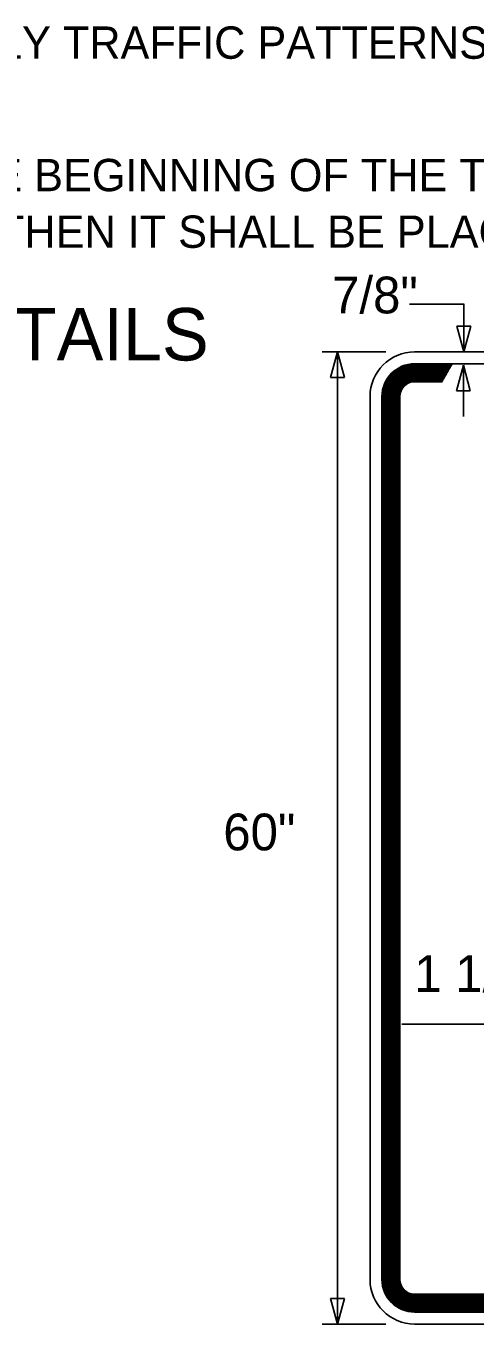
# Model space of a CAD drawing. Extents: x 15262 to 18126, y 1908 to 6555.
# Drawn here: x 17745 to 17847.7, y 2366.5 to 2663.3 of the extents above; entities that cross this region are included whole.
import ezdxf

# ---------------------------------------------------------------- set-up
doc = ezdxf.new("R2010")
doc.units = 0
doc.layers.add('TYPICAL_EX', color=7, linetype='Continuous')
doc.layers.add('TYPICAL_TEXT_DIMEN_PR', color=7, linetype='Continuous')

msp = doc.modelspace()

# ---------------------------------------------------------------- linework, layer by layer
at = {"layer": 'TYPICAL_EX'}
for p, q in [((17976.4, 2588.82), (17833.88, 2588.82)), ((17842.58, 2586.1), (17833.89, 2586.1)), ((17842.52, 2585.99), (17833.89, 2585.99)), ((17842.45, 2585.88), (17833.89, 2585.88)), ((17842.39, 2585.77), (17833.89, 2585.77)), ((17842.32, 2585.66), (17833.89, 2585.66)), ((17842.26, 2585.54), (17833.89, 2585.54)), ((17842.19, 2585.43), (17833.89, 2585.43)), ((17842.13, 2585.32), (17833.89, 2585.32)), ((17846.51, 2586.1), (17842.51, 2586.1)), ((17976.4, 2586.1), (17846.51, 2586.1)), ((17842.06, 2585.21), (17833.89, 2585.21)), ((17842, 2585.1), (17833.89, 2585.1)), ((17841.94, 2584.98), (17833.89, 2584.98)), ((17841.87, 2584.87), (17833.89, 2584.87)), ((17841.81, 2584.76), (17833.89, 2584.76)), ((17841.74, 2584.65), (17833.89, 2584.65)), ((17841.68, 2584.53), (17833.89, 2584.53)), ((17841.61, 2584.42), (17833.89, 2584.42)), ((17841.55, 2584.31), (17833.89, 2584.31)), ((17841.48, 2584.2), (17833.89, 2584.2)), ((17841.42, 2584.09), (17833.89, 2584.09)), ((17841.35, 2583.97), (17833.89, 2583.97)), ((17841.29, 2583.86), (17833.89, 2583.86)), ((17841.22, 2583.75), (17833.89, 2583.75)), ((17841.16, 2583.64), (17833.89, 2583.64)), ((17841.1, 2583.53), (17833.89, 2583.53)), ((17841.03, 2583.41), (17833.89, 2583.41)), ((17840.97, 2583.3), (17833.89, 2583.3)), ((17840.9, 2583.19), (17833.89, 2583.19)), ((17840.84, 2583.08), (17833.89, 2583.08)), ((17840.77, 2582.97), (17833.89, 2582.97)), ((17840.71, 2582.85), (17833.89, 2582.85)), ((17840.64, 2582.74), (17833.89, 2582.74)), ((17840.58, 2582.63), (17833.89, 2582.63)), ((17840.51, 2582.52), (17833.89, 2582.52)), ((17840.45, 2582.41), (17833.89, 2582.41)), ((17840.39, 2582.29), (17833.89, 2582.29)), ((17840.32, 2582.18), (17833.89, 2582.18)), ((17840.26, 2582.07), (17833.89, 2582.07)), ((17840.21, 2581.99), (17833.89, 2581.99)), ((17823.7, 2578.64), (17823.7, 2430.55)), ((17826.42, 2578.64), (17826.42, 2430.55)), ((17826.53, 2578.64), (17826.53, 2430.55)), ((17826.64, 2578.64), (17826.64, 2430.55)), ((17826.76, 2578.64), (17826.76, 2430.55)), ((17826.87, 2578.64), (17826.87, 2430.42)), ((17826.98, 2578.64), (17826.98, 2430.55)), ((17827.09, 2578.64), (17827.09, 2430.55)), ((17827.2, 2578.64), (17827.2, 2430.53)), ((17827.32, 2578.64), (17827.32, 2430.56)), ((17827.43, 2578.64), (17827.43, 2430.51)), ((17827.54, 2578.64), (17827.54, 2430.55)), ((17827.65, 2578.64), (17827.65, 2430.55)), ((17827.76, 2578.64), (17827.76, 2430.59)), ((17827.88, 2578.64), (17827.88, 2430.55)), ((17827.99, 2578.64), (17827.99, 2430.55)), ((17828.1, 2578.64), (17828.1, 2430.55)), ((17828.21, 2578.64), (17828.21, 2430.55)), ((17828.33, 2578.64), (17828.33, 2430.55)), ((17828.44, 2578.64), (17828.44, 2430.54)), ((17828.55, 2578.64), (17828.55, 2430.55)), ((17828.66, 2578.64), (17828.66, 2430.56)), ((17828.77, 2578.64), (17828.77, 2430.55)), ((17828.89, 2578.64), (17828.89, 2430.55)), ((17829, 2578.64), (17829, 2430.54)), ((17829.11, 2578.64), (17829.11, 2430.57)), ((17829.22, 2578.64), (17829.22, 2430.55)), ((17829.33, 2578.64), (17829.33, 2430.55)), ((17829.44, 2578.64), (17829.44, 2449.25)), ((17829.56, 2578.64), (17829.56, 2449.25)), ((17829.67, 2578.64), (17829.67, 2449.25)), ((17829.78, 2578.64), (17829.78, 2430.55)), ((17829.89, 2578.64), (17829.89, 2430.54)), ((17830.01, 2578.64), (17830.01, 2430.55)), ((17830.12, 2578.64), (17830.12, 2430.54)), ((17830.23, 2578.64), (17830.23, 2430.55)), ((17830.34, 2578.64), (17830.34, 2430.57)), ((17830.45, 2578.64), (17830.45, 2430.56)), ((17830.53, 2578.64), (17830.53, 2430.57)), ((17829.44, 2449.33), (17829.44, 2376.7)), ((17829.56, 2449.25), (17829.56, 2376.7)), ((17829.67, 2449.25), (17829.67, 2376.7)), ((17830.94, 2435.12), (17979.69, 2435.12)), ((17823.7, 2430.55), (17823.7, 2376.7)), ((17826.42, 2430.55), (17826.42, 2376.7)), ((17826.53, 2430.55), (17826.53, 2376.7)), ((17826.64, 2430.55), (17826.64, 2376.7)), ((17826.76, 2430.55), (17826.76, 2376.7)), ((17826.87, 2430.55), (17826.87, 2376.7)), ((17826.98, 2430.55), (17826.98, 2376.7)), ((17827.09, 2430.55), (17827.09, 2376.7)), ((17827.2, 2430.55), (17827.2, 2376.03)), ((17827.32, 2430.55), (17827.32, 2376.7)), ((17827.43, 2430.55), (17827.43, 2376.7)), ((17827.54, 2430.55), (17827.54, 2376.7)), ((17827.65, 2430.55), (17827.65, 2376.7)), ((17827.76, 2430.6), (17827.76, 2376.7)), ((17827.88, 2430.55), (17827.88, 2376.7)), ((17827.99, 2430.55), (17827.99, 2376.7)), ((17828.1, 2430.55), (17828.1, 2376.7)), ((17828.21, 2430.55), (17828.21, 2376.7)), ((17828.33, 2430.55), (17828.33, 2376.7)), ((17828.44, 2430.55), (17828.44, 2376.7)), ((17828.55, 2430.55), (17828.55, 2376.7)), ((17828.66, 2430.55), (17828.66, 2376.7)), ((17828.77, 2430.55), (17828.77, 2376.7)), ((17828.89, 2430.55), (17828.89, 2376.7)), ((17829, 2430.55), (17829, 2376.7)), ((17829.11, 2430.55), (17829.11, 2376.7)), ((17829.22, 2430.55), (17829.22, 2376.7)), ((17829.33, 2430.55), (17829.33, 2376.7)), ((17829.78, 2430.55), (17829.78, 2376.7)), ((17829.89, 2430.55), (17829.89, 2376.7)), ((17830.01, 2430.55), (17830.01, 2376.7)), ((17830.12, 2430.54), (17830.12, 2376.7)), ((17830.23, 2430.55), (17830.23, 2376.7)), ((17830.34, 2430.55), (17830.34, 2376.7)), ((17830.45, 2430.55), (17830.45, 2376.7)), ((17830.53, 2430.55), (17830.53, 2376.7)), ((17833.88, 2373.35), (17976.4, 2373.35)), ((17833.88, 2373.27), (17976.4, 2373.27)), ((17833.88, 2373.16), (17976.4, 2373.16)), ((17833.88, 2373.05), (17976.4, 2373.05)), ((17833.88, 2372.94), (17976.4, 2372.94)), ((17833.88, 2372.83), (17976.4, 2372.83)), ((17833.88, 2372.71), (17976.4, 2372.71)), ((17833.88, 2372.6), (17976.4, 2372.6)), ((17833.88, 2372.49), (17976.4, 2372.49)), ((17833.88, 2372.38), (17976.4, 2372.38)), ((17833.88, 2372.27), (17976.4, 2372.27)), ((17833.88, 2372.15), (17976.4, 2372.15)), ((17833.88, 2372.04), (17976.4, 2372.04)), ((17833.88, 2371.93), (17976.4, 2371.93)), ((17833.88, 2371.82), (17976.4, 2371.82)), ((17833.88, 2371.7), (17976.4, 2371.7)), ((17833.88, 2371.59), (17976.4, 2371.59)), ((17833.88, 2371.48), (17976.4, 2371.48)), ((17833.88, 2371.37), (17976.4, 2371.37)), ((17833.88, 2371.26), (17976.4, 2371.26)), ((17833.88, 2371.14), (17976.4, 2371.14)), ((17833.88, 2371.03), (17976.4, 2371.03)), ((17833.88, 2370.92), (17976.4, 2370.92)), ((17833.88, 2370.81), (17976.4, 2370.81)), ((17833.88, 2370.7), (17976.4, 2370.7)), ((17833.88, 2370.59), (17976.4, 2370.59)), ((17833.88, 2370.47), (17976.4, 2370.47)), ((17833.88, 2370.36), (17976.4, 2370.36)), ((17833.88, 2370.25), (17976.4, 2370.25)), ((17833.88, 2370.14), (17976.4, 2370.14)), ((17833.88, 2370.02), (17976.4, 2370.02)), ((17833.88, 2369.91), (17976.4, 2369.91)), ((17833.88, 2369.8), (17976.4, 2369.8)), ((17833.88, 2369.69), (17976.4, 2369.69)), ((17833.88, 2369.58), (17976.4, 2369.58)), ((17833.88, 2369.46), (17976.4, 2369.46)), ((17833.88, 2369.35), (17976.4, 2369.35)), ((17833.88, 2369.24), (17976.4, 2369.24)), ((17833.88, 2366.53), (17976.4, 2366.53))]:
    msp.add_line(p, q, dxfattribs=at)
for centre, radius, start, end in [((17833.88, 2578.64), 10.18, 90, 180), ((17833.88, 2578.64), 7.46, 90, 180), ((17833.88, 2578.64), 7.35, 90, 180), ((17833.88, 2578.64), 7.24, 90, 180), ((17833.88, 2578.64), 7.13, 90, 180), ((17833.88, 2578.64), 7.02, 90, 180), ((17833.88, 2578.64), 6.9, 90, 180), ((17833.88, 2578.64), 6.79, 90, 180), ((17833.88, 2578.64), 6.68, 90, 180), ((17833.88, 2578.64), 6.57, 90, 180), ((17833.88, 2578.64), 6.46, 90, 180), ((17833.88, 2578.64), 6.34, 90, 180), ((17833.88, 2578.64), 6.23, 90, 180), ((17833.88, 2578.64), 6.12, 90, 180), ((17833.88, 2578.64), 6.01, 90, 180), ((17833.88, 2578.64), 5.9, 90, 180), ((17833.88, 2578.64), 5.78, 90, 180), ((17833.88, 2578.64), 5.67, 90, 180), ((17833.88, 2578.64), 5.56, 90, 180), ((17833.88, 2578.64), 5.45, 90, 180), ((17833.88, 2578.64), 5.34, 90, 180), ((17833.88, 2578.64), 5.22, 90, 180), ((17833.88, 2578.64), 5.11, 90, 180), ((17833.88, 2578.64), 5, 90, 180), ((17833.88, 2578.64), 4.89, 90, 180), ((17833.88, 2578.64), 4.78, 90, 180), ((17833.88, 2578.64), 4.66, 90, 180), ((17833.88, 2578.64), 4.55, 90, 180), ((17833.88, 2578.64), 4.44, 90, 180), ((17833.88, 2578.64), 4.33, 90, 180), ((17833.88, 2578.64), 4.21, 90, 180), ((17833.88, 2578.64), 4.1, 90, 180), ((17833.88, 2578.64), 3.99, 90, 180), ((17833.88, 2578.64), 3.88, 90, 180), ((17833.88, 2578.64), 3.77, 90, 180), ((17833.88, 2578.64), 3.65, 90, 180), ((17833.88, 2578.64), 3.54, 90, 180), ((17833.88, 2578.64), 3.43, 90, 180), ((17833.88, 2578.64), 3.36, 90, 180), ((17833.88, 2376.71), 10.18, 180, 270), ((17833.88, 2376.71), 7.46, 180, 270), ((17833.88, 2376.71), 7.35, 180, 270), ((17833.88, 2376.71), 7.24, 180, 270), ((17833.88, 2376.71), 7.13, 180, 270), ((17833.88, 2376.71), 7.02, 180, 270), ((17833.88, 2376.71), 6.9, 180, 270), ((17833.88, 2376.71), 6.79, 180, 270), ((17833.88, 2376.71), 6.68, 180, 270), ((17833.88, 2376.71), 6.57, 180, 270), ((17833.88, 2376.71), 6.46, 180, 270), ((17833.88, 2376.71), 6.34, 180, 270), ((17833.88, 2376.71), 6.23, 180, 270), ((17833.88, 2376.71), 6.12, 180, 270), ((17833.88, 2376.71), 6.01, 180, 270), ((17833.88, 2376.71), 5.9, 180, 270), ((17833.88, 2376.71), 5.78, 180, 270), ((17833.88, 2376.71), 5.67, 180, 270), ((17833.88, 2376.71), 5.56, 180, 270), ((17833.88, 2376.71), 5.45, 180, 270), ((17833.88, 2376.71), 5.34, 180, 270), ((17833.88, 2376.71), 5.22, 180, 270), ((17833.88, 2376.71), 5.11, 180, 270), ((17833.88, 2376.71), 5, 180, 270), ((17833.88, 2376.71), 4.89, 180, 270), ((17833.88, 2376.71), 4.78, 180, 270), ((17833.88, 2376.71), 4.66, 180, 270), ((17833.88, 2376.71), 4.55, 180, 270), ((17833.88, 2376.71), 4.44, 180, 270), ((17833.88, 2376.71), 4.33, 180, 270), ((17833.88, 2376.71), 4.21, 180, 270), ((17833.88, 2376.71), 4.1, 180, 270), ((17833.88, 2376.71), 3.99, 180, 270), ((17833.88, 2376.71), 3.88, 180, 270), ((17833.88, 2376.71), 3.77, 180, 270), ((17833.88, 2376.71), 3.65, 180, 270), ((17833.88, 2376.71), 3.54, 180, 270), ((17833.88, 2376.71), 3.43, 180, 270), ((17833.88, 2376.71), 3.36, 180, 270)]:
    msp.add_arc(centre, radius, start, end, dxfattribs=at)
at = {"layer": 'TYPICAL_TEXT_DIMEN_PR'}
for p, q in [((17832.69, 2599.74), (17845.14, 2599.72)), ((17845.14, 2588.82), (17845.13, 2599.82)), ((17845.14, 2588.82), (17843.57, 2594.68)), ((17843.57, 2594.68), (17845.14, 2594.68)), ((17845.14, 2594.68), (17846.71, 2594.68)), ((17846.71, 2594.68), (17845.14, 2588.82)), ((17827.33, 2588.82), (17812.72, 2588.82)), ((17814.69, 2582.96), (17816.26, 2588.82)), ((17816.26, 2430.55), (17816.26, 2588.82)), ((17816.26, 2588.82), (17817.83, 2582.96)), ((17843.48, 2579.91), (17845.03, 2585.77)), ((17845.06, 2574.06), (17845.03, 2585.77)), ((17845.03, 2585.77), (17846.62, 2579.91)), ((17816.26, 2582.96), (17814.69, 2582.96)), ((17817.83, 2582.96), (17816.26, 2582.96)), ((17845.05, 2579.91), (17843.48, 2579.91)), ((17846.62, 2579.91), (17845.05, 2579.91)), ((17816.26, 2366.53), (17816.26, 2430.55)), ((17816.26, 2366.53), (17814.69, 2372.39)), ((17814.69, 2372.39), (17816.26, 2372.39)), ((17816.26, 2372.39), (17817.83, 2372.39)), ((17817.83, 2372.39), (17816.26, 2366.53)), ((17827.33, 2366.53), (17812.72, 2366.53))]:
    msp.add_line(p, q, dxfattribs=at)

# ---------------------------------------------------------------- texts
for s, height, p in [('PATTERN.  EXCEPTION WILL BE MADE FOR DAYTIME-ONLY TRAFFIC PATTERNS THAT ARE ADEQUATELY DELINEATED BY', 7.392, (17465.67, 2655.84)), ('THE LIGHTED ARROW PANEL SHALL BE LOCATED AT THE BEGINNING OF THE TAPER AS SHOWN.  WHEN PHYSICAL', 7.392, (17465.67, 2625.55)), ('LIMITATIONS RESTRICT ITS PLACEMENT AS INDICATED, THEN IT SHALL BE PLACED AS CLOSE TO THE BEGINNING', 7.392, (17465.67, 2612.61)), ('7/8"', 8.4, (17815.02, 2597.62)), ('SIGN DETAILS', 12, (17676.24, 2586.85)), ('60"', 8.4, (17790.14, 2474.84)), ('1 1/4"', 8.4, (17833.8, 2442.45))]:
    msp.add_text(s, height=height, dxfattribs=at).set_placement(p)

doc.saveas('drawing.dxf')
